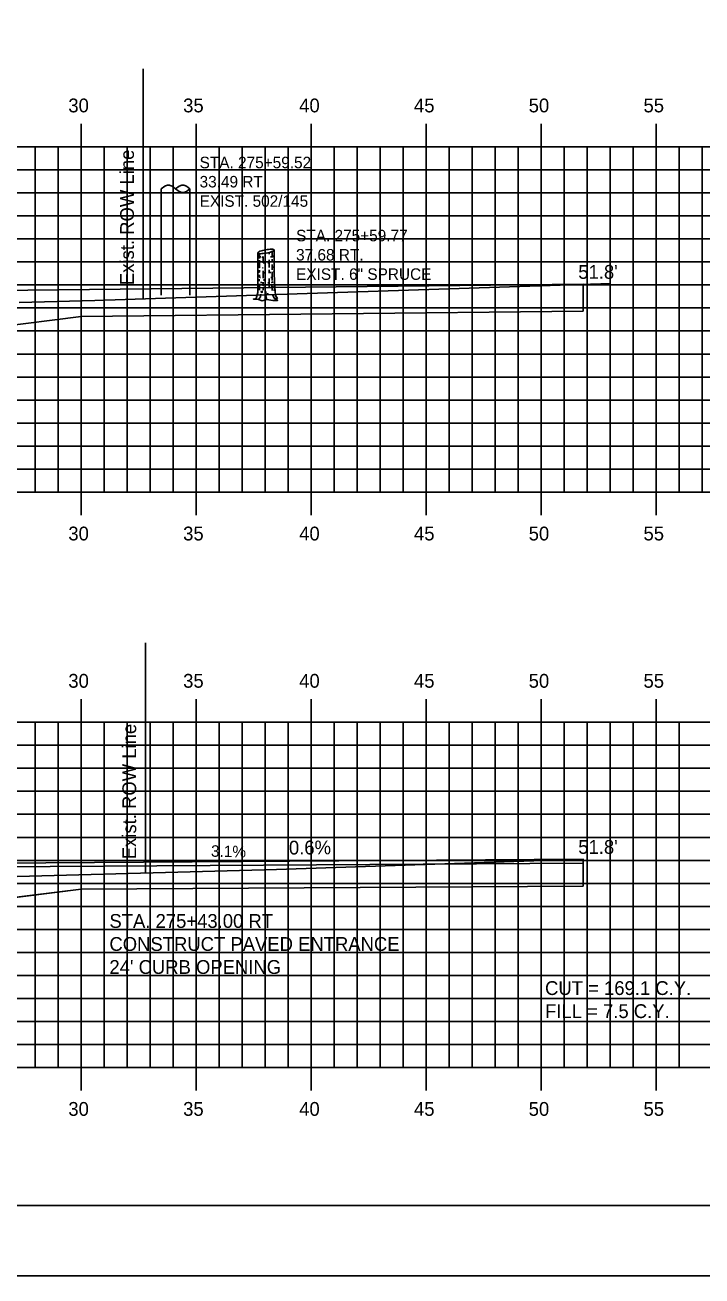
# Model space of a CAD drawing. Extents: x 853563 to 853733, y 366268 to 366378.
# Drawn here: x 853673.3 to 853702.8, y 366268.2 to 366322.5 of the extents above; entities that cross this region are included whole.
import ezdxf

# ---------------------------------------------------------------- set-up
doc = ezdxf.new("R2010")
doc.units = 0
for name, color, linetype in [('ANNOTATION', 7, 'Continuous'), ('BORDER', 7, 'Continuous'), ('D_Roadway_Drive_Gravel_RT', 7, 'Continuous'), ('D_Roadway_Drive_SubGrade', 7, 'Continuous'), ('D_Text_Monospaced', 7, 'Continuous'), ('D_Text_Standard', 7, 'Continuous'), ('E_ROW_Line', 7, 'Continuous'), ('H_V ANNOTATION', 7, 'Continuous'), ('JUNK COM EXC', 7, 'Continuous'), ('MAJOR', 7, 'Continuous'), ('MINOR', 7, 'Continuous'), ('PLOT BOUNDARY', 7, 'Continuous'), ('S_Roadway_Centerline', 7, 'Continuous'), ('S_Trees_Conifer_NonPay', 7, 'Continuous'), ('S_Utilities_Pole_Power', 7, 'Continuous')]:
    doc.layers.add(name, color=color, linetype=linetype)

msp = doc.modelspace()

# ---------------------------------------------------------------- linework, layer by layer
at = {"layer": 'BORDER'}
msp.add_line((853570.768, 366271.236), (853730.768, 366271.236), dxfattribs=at)
at = {"layer": 'D_Roadway_Drive_Gravel_RT'}
for p, q in [((853669.768, 366310.963), (853697.603, 366311.267)), ((853675.768, 366309.862), (853697.603, 366310.1)), ((853669.764, 366286.106), (853697.603, 366286.284)), ((853669.765, 366285.939), (853697.603, 366286.117)), ((853675.768, 366284.977), (853697.603, 366285.117))]:
    msp.add_line(p, q, dxfattribs=at)
at = {"layer": 'D_Roadway_Drive_SubGrade'}
for p, q in [((853697.603, 366311.267), (853697.603, 366310.1)), ((853665.758, 366308.61), (853675.768, 366309.862)), ((853697.603, 366286.284), (853697.603, 366285.117)), ((853665.774, 366283.753), (853675.768, 366284.977))]:
    msp.add_line(p, q, dxfattribs=at)
at = {"layer": 'E_ROW_Line'}
for p, q in [((853678.469, 366310.63), (853678.469, 366320.63)), ((853678.565, 366285.683), (853678.565, 366295.683))]:
    msp.add_line(p, q, dxfattribs=at)
at = {"layer": 'JUNK COM EXC'}
msp.add_lwpolyline([(853697.603, 366285.117), (853697.603, 366286.284), (853684.27, 366285.84), (853672.991, 366285.531), (853672.225, 366285.511), (853671.472, 366285.595), (853665.766, 366285.75), (853665.774, 366283.753), (853675.768, 366284.977), (853697.603, 366285.117)], dxfattribs=at)
at = {"layer": 'MAJOR'}
for p, q in [((853675.768, 366318.238), (853675.768, 366317.236)), ((853680.768, 366318.238), (853680.768, 366317.236)), ((853685.768, 366318.238), (853685.768, 366317.236)), ((853690.768, 366318.238), (853690.768, 366317.236)), ((853695.768, 366318.238), (853695.768, 366317.236)), ((853700.768, 366318.238), (853700.768, 366317.236)), ((853575.768, 366317.236), (853715.768, 366317.236)), ((853575.768, 366317.236), (853715.768, 366317.236)), ((853675.768, 366302.236), (853675.768, 366317.236)), ((853680.768, 366302.236), (853680.768, 366317.236)), ((853685.768, 366302.236), (853685.768, 366317.236)), ((853690.768, 366302.236), (853690.768, 366317.236)), ((853695.768, 366302.236), (853695.768, 366317.236)), ((853700.768, 366302.236), (853700.768, 366317.236)), ((853575.768, 366312.236), (853715.768, 366312.236)), ((853575.768, 366307.236), (853715.768, 366307.236)), ((853575.768, 366302.236), (853715.768, 366302.236)), ((853575.768, 366302.236), (853715.768, 366302.236)), ((853675.768, 366301.234), (853675.768, 366302.236)), ((853680.768, 366301.234), (853680.768, 366302.236)), ((853685.768, 366301.234), (853685.768, 366302.236)), ((853690.768, 366301.234), (853690.768, 366302.236)), ((853695.768, 366301.234), (853695.768, 366302.236)), ((853700.768, 366301.234), (853700.768, 366302.236)), ((853675.768, 366293.238), (853675.768, 366292.236)), ((853680.768, 366293.238), (853680.768, 366292.236)), ((853685.768, 366293.238), (853685.768, 366292.236)), ((853690.768, 366293.238), (853690.768, 366292.236)), ((853695.768, 366293.238), (853695.768, 366292.236)), ((853700.768, 366293.238), (853700.768, 366292.236)), ((853575.768, 366292.236), (853715.768, 366292.236)), ((853575.768, 366292.236), (853715.768, 366292.236)), ((853675.768, 366277.236), (853675.768, 366292.236)), ((853680.768, 366277.236), (853680.768, 366292.236)), ((853685.768, 366277.236), (853685.768, 366292.236)), ((853690.768, 366277.236), (853690.768, 366292.236)), ((853695.768, 366277.236), (853695.768, 366292.236)), ((853700.768, 366277.236), (853700.768, 366292.236)), ((853575.768, 366287.236), (853715.768, 366287.236)), ((853575.768, 366282.236), (853715.768, 366282.236)), ((853575.768, 366277.236), (853715.768, 366277.236)), ((853575.768, 366277.236), (853715.768, 366277.236)), ((853675.768, 366276.234), (853675.768, 366277.236)), ((853680.768, 366276.234), (853680.768, 366277.236)), ((853685.768, 366276.234), (853685.768, 366277.236)), ((853690.768, 366276.234), (853690.768, 366277.236)), ((853695.768, 366276.234), (853695.768, 366277.236)), ((853700.768, 366276.234), (853700.768, 366277.236))]:
    msp.add_line(p, q, dxfattribs=at)
at = {"layer": 'MINOR'}
for p, q in [((853673.768, 366302.236), (853673.768, 366317.236)), ((853674.768, 366302.236), (853674.768, 366317.236)), ((853676.768, 366302.236), (853676.768, 366317.236)), ((853677.768, 366302.236), (853677.768, 366317.236)), ((853678.768, 366302.236), (853678.768, 366317.236)), ((853679.768, 366302.236), (853679.768, 366317.236)), ((853681.768, 366302.236), (853681.768, 366317.236)), ((853682.768, 366302.236), (853682.768, 366317.236)), ((853683.768, 366302.236), (853683.768, 366317.236)), ((853684.768, 366302.236), (853684.768, 366317.236)), ((853686.768, 366302.236), (853686.768, 366317.236)), ((853687.768, 366302.236), (853687.768, 366317.236)), ((853688.768, 366302.236), (853688.768, 366317.236)), ((853689.768, 366302.236), (853689.768, 366317.236)), ((853691.768, 366302.236), (853691.768, 366317.236)), ((853692.768, 366302.236), (853692.768, 366317.236)), ((853693.768, 366302.236), (853693.768, 366317.236)), ((853694.768, 366302.236), (853694.768, 366317.236)), ((853696.768, 366302.236), (853696.768, 366317.236)), ((853697.768, 366302.236), (853697.768, 366317.236)), ((853698.768, 366302.236), (853698.768, 366317.236)), ((853699.768, 366302.236), (853699.768, 366317.236)), ((853701.768, 366302.236), (853701.768, 366317.236)), ((853702.768, 366302.236), (853702.768, 366317.236)), ((853575.768, 366316.236), (853715.768, 366316.236)), ((853575.768, 366315.236), (853715.768, 366315.236)), ((853575.768, 366314.236), (853715.768, 366314.236)), ((853575.768, 366313.236), (853715.768, 366313.236)), ((853575.768, 366311.236), (853715.768, 366311.236)), ((853575.768, 366310.236), (853715.768, 366310.236)), ((853575.768, 366309.236), (853715.768, 366309.236)), ((853575.768, 366308.236), (853715.768, 366308.236)), ((853575.768, 366306.236), (853715.768, 366306.236)), ((853575.768, 366305.236), (853715.768, 366305.236)), ((853575.768, 366304.236), (853715.768, 366304.236)), ((853575.768, 366303.236), (853715.768, 366303.236)), ((853673.768, 366277.236), (853673.768, 366292.236)), ((853674.768, 366277.236), (853674.768, 366292.236)), ((853676.768, 366277.236), (853676.768, 366292.236)), ((853677.768, 366277.236), (853677.768, 366292.236)), ((853678.768, 366277.236), (853678.768, 366292.236)), ((853679.768, 366277.236), (853679.768, 366292.236)), ((853681.768, 366277.236), (853681.768, 366292.236)), ((853682.768, 366277.236), (853682.768, 366292.236)), ((853683.768, 366277.236), (853683.768, 366292.236)), ((853684.768, 366277.236), (853684.768, 366292.236)), ((853686.768, 366277.236), (853686.768, 366292.236)), ((853687.768, 366277.236), (853687.768, 366292.236)), ((853688.768, 366277.236), (853688.768, 366292.236)), ((853689.768, 366277.236), (853689.768, 366292.236)), ((853691.768, 366277.236), (853691.768, 366292.236)), ((853692.768, 366277.236), (853692.768, 366292.236)), ((853693.768, 366277.236), (853693.768, 366292.236)), ((853694.768, 366277.236), (853694.768, 366292.236)), ((853696.768, 366277.236), (853696.768, 366292.236)), ((853697.768, 366277.236), (853697.768, 366292.236)), ((853698.768, 366277.236), (853698.768, 366292.236)), ((853699.768, 366277.236), (853699.768, 366292.236)), ((853701.768, 366277.236), (853701.768, 366292.236)), ((853575.768, 366291.236), (853715.768, 366291.236)), ((853575.768, 366290.236), (853715.768, 366290.236)), ((853575.768, 366289.236), (853715.768, 366289.236)), ((853575.768, 366288.236), (853715.768, 366288.236)), ((853575.768, 366286.236), (853715.768, 366286.236)), ((853575.768, 366285.236), (853715.768, 366285.236)), ((853575.768, 366284.236), (853715.768, 366284.236)), ((853575.768, 366283.236), (853715.768, 366283.236)), ((853575.768, 366281.236), (853715.768, 366281.236)), ((853575.768, 366280.236), (853715.768, 366280.236)), ((853575.768, 366279.236), (853715.768, 366279.236)), ((853575.768, 366278.236), (853715.768, 366278.236))]:
    msp.add_line(p, q, dxfattribs=at)
at = {"layer": 'PLOT BOUNDARY'}
msp.add_lwpolyline([(853562.674, 366268.177), (853732.674, 366268.177), (853732.674, 366378.177), (853562.674, 366378.177)], close=True, dxfattribs=at)
at = {"layer": 'S_Roadway_Centerline'}
for points in [[(853673.078, 366310.47), (853676.362, 366310.56), (853698.798, 366311.307)], [(853672.991, 366285.531), (853684.27, 366285.84), (853697.603, 366286.284)]]:
    msp.add_lwpolyline(points, dxfattribs=at)
at = {"layer": 'S_Trees_Conifer_NonPay'}
for p, q in [((853683.53, 366312.596), (853683.53, 366312.39)), ((853683.687, 366312.471), (853683.687, 366312.197)), ((853683.949, 366312.651), (853683.949, 366312.572)), ((853684.083, 366312.362), (853684.083, 366312.232)), ((853683.53, 366312.318), (853683.53, 366311.986)), ((853683.53, 366311.872), (853683.53, 366311.793)), ((853683.687, 366311.844), (853683.687, 366311.526)), ((853683.949, 366312.323), (853683.949, 366311.997)), ((853683.949, 366311.896), (853683.949, 366311.743)), ((853684.083, 366312.123), (853684.083, 366311.896)), ((853684.083, 366311.804), (853684.083, 366311.428)), ((853683.513, 366311.492), (853683.513, 366311.395)), ((853683.53, 366311.679), (853683.53, 366311.569)), ((853683.53, 366311.281), (853683.53, 366311.013)), ((853683.687, 366311.356), (853683.687, 366311.196)), ((853683.728, 366311.481), (853683.728, 366311.411)), ((853683.949, 366311.514), (853683.949, 366311.281)), ((853683.687, 366311.138), (853683.687, 366311.007)), ((853683.949, 366311.218), (853683.949, 366311.132)), ((853684.065, 366311.235), (853684.082, 366310.99)), ((853684.144, 366311.007), (853684.204, 366311.014))]:
    msp.add_line(p, q, dxfattribs=at)
for points in [[(853683.452, 366312.63), (853683.452, 366310.912), (853683.382, 366310.655), (853683.263, 366310.621), (853683.479, 366310.605), (853683.639, 366310.547), (853683.848, 366310.605), (853684.11, 366310.558), (853684.316, 366310.564), (853684.165, 366310.667), (853684.093, 366310.82)], [(853684.083, 366312.692), (853684.083, 366312.594), (853684.083, 366312.43)], [(853684.194, 366310.646), (853684.31, 366310.655), (853684.219, 366310.781), (853684.185, 366311.321), (853684.165, 366311.839), (853684.165, 366312.758)], [(853683.479, 366310.605), (853683.569, 366310.717), (853683.586, 366310.831)], [(853683.61, 366310.968), (853683.599, 366310.923), (853683.65, 366310.912), (853683.65, 366310.974)], [(853683.848, 366310.605), (853683.803, 366310.781), (853683.797, 366310.945)], [(853683.801, 366310.831), (853683.871, 366310.825), (853683.889, 366310.878)]]:
    msp.add_lwpolyline(points, dxfattribs=at)
for centre, radius, start, end in [((853683.466, 366312.63), 0.0141, 174.3267, 190.3798), ((853683.47, 366312.63), 0.0186, 160.3798, 174.3267), ((853683.466, 366312.63), 0.0141, 190.3798, 206.433), ((853683.466, 366312.514), 0.0143, 180, 196.0515), ((853683.477, 366312.627), 0.0263, 141.6195, 160.3798), ((853683.47, 366312.632), 0.0186, 206.433, 220.3798), ((853683.475, 366312.637), 0.0263, 220.3798, 239.1402), ((853683.514, 366312.598), 0.0729, 130.3798, 141.6195), ((853683.499, 366312.677), 0.0729, 239.1402, 250.3798), ((853683.625, 366312.467), 0.245, 108.3946, 130.3798), ((853683.557, 366312.839), 0.245, 250.3798, 272.3651), ((853683.594, 366312.703), 0.245, 254.8461, 261.8968), ((853684.124, 366310.967), 1.825, 100.3798, 108.3946), ((853683.809, 366314.21), 1.767, 261.8968, 262.605), ((853683.492, 366314.418), 1.825, 272.3651, 280.3798), ((853683.809, 366314.21), 1.767, 264.3267, 266.0499), ((853684.124, 366310.967), 1.825, 92.3651, 100.3798), ((853683.492, 366314.418), 1.825, 280.3798, 288.3946), ((853683.809, 366314.21), 1.767, 276.2449, 278.1032), ((853684.059, 366312.546), 0.245, 70.3798, 92.3651), ((853684.023, 366312.703), 0.245, 278.1032, 284.1859), ((853683.991, 366312.919), 0.245, 288.3946, 310.3798), ((853684.023, 366312.703), 0.245, 291.7653, 300), ((853684.117, 366312.708), 0.0729, 59.1402, 70.3798), ((853684.109, 366312.555), 0.0738, 300, 311.2506), ((853684.102, 366312.787), 0.0729, 310.3798, 321.6195), ((853684.141, 366312.748), 0.0263, 40.3798, 59.1402), ((853684.14, 366312.519), 0.0267, 311.2506, 330), ((853684.139, 366312.759), 0.0263, 321.6195, 340.3798), ((853684.147, 366312.753), 0.0186, 26.433, 40.3798), ((853684.151, 366312.755), 0.0141, 10.3798, 26.433), ((853684.146, 366312.515), 0.0189, 330, 343.9485), ((853684.151, 366312.755), 0.0141, 354.3267, 10.3798), ((853684.146, 366312.756), 0.0186, 340.3798, 354.3267), ((853683.466, 366312.048), 0.0143, 180, 196.0515), ((853683.467, 366311.837), 0.0143, 180, 196.0515), ((853683.471, 366312.049), 0.0189, 196.0515, 210), ((853683.471, 366311.838), 0.0189, 196.0515, 210), ((853683.478, 366312.053), 0.0267, 210, 228.7494), ((853683.478, 366311.842), 0.0267, 210, 228.7494), ((853683.509, 366312.089), 0.0738, 228.7494, 240), ((853683.509, 366311.877), 0.0738, 228.7494, 240), ((853683.594, 366312.237), 0.245, 240, 246.7914), ((853683.594, 366312.025), 0.245, 240, 254.9514), ((853683.596, 366312.45), 0.245, 244.3148, 257.5375), ((853683.594, 366312.237), 0.245, 254.8461, 257.5454), ((853683.809, 366313.744), 1.767, 265.2285, 266.1325), ((853683.81, 366313.958), 1.767, 265.8991, 267.5962), ((853683.81, 366313.958), 1.767, 272.7221, 274.4847), ((853684.023, 366312.237), 0.245, 284.1859, 300), ((853684.023, 366312.025), 0.245, 292.1924, 300), ((853684.109, 366312.089), 0.0738, 300, 311.2506), ((853684.109, 366311.877), 0.0738, 300, 311.2506), ((853684.14, 366312.053), 0.0267, 311.2506, 330), ((853684.14, 366311.842), 0.0267, 311.2506, 330), ((853684.141, 366312.267), 0.0267, 311.2506, 330), ((853684.146, 366312.049), 0.0189, 330, 343.9485), ((853684.147, 366311.838), 0.0189, 330, 343.9485), ((853684.148, 366312.263), 0.0189, 330, 343.9485), ((853683.466, 366311.4), 0.0143, 180, 196.0515), ((853683.593, 366311.806), 0.245, 254.9814, 261.8968), ((853683.808, 366313.313), 1.767, 261.8968, 262.45), ((853683.808, 366313.096), 1.767, 262.2622, 265.0496), ((853683.809, 366313.533), 1.767, 266.0429, 268.5525), ((853683.808, 366313.096), 1.767, 272.6293, 274.5612), ((853683.809, 366313.533), 1.767, 274.5361, 277.0026), ((853683.808, 366313.313), 1.767, 276.7966, 278.1032), ((853683.808, 366313.096), 1.767, 277.63, 278.1032), ((853684.023, 366311.806), 0.245, 278.1032, 284.3207), ((853684.023, 366311.589), 0.245, 278.1032, 294.6056), ((853683.465, 366311.195), 0.0143, 180, 196.0515), ((853683.47, 366311.196), 0.0189, 196.0515, 210), ((853683.476, 366311.2), 0.0267, 210, 228.7494), ((853683.507, 366311.235), 0.0738, 228.7494, 240), ((853683.593, 366311.383), 0.245, 240, 249.1675), ((853683.807, 366312.891), 1.767, 266.0862, 268.2187), ((853683.807, 366312.891), 1.767, 274.2776, 276.3006), ((853684.022, 366311.383), 0.245, 284.0684, 300), ((853684.108, 366311.235), 0.0738, 300, 302.05)]:
    msp.add_arc(centre, radius, start, end, dxfattribs=at)
at = {"layer": 'S_Utilities_Pole_Power'}
for p, q in [((853679.256, 366310.793), (853679.253, 366315.413)), ((853679.256, 366315.413), (853679.413, 366315.523)), ((853679.725, 366315.523), (853679.881, 366315.413)), ((853680.038, 366315.523), (853679.881, 366315.413)), ((853679.881, 366315.413), (853680.038, 366315.302)), ((853680.506, 366315.413), (853680.35, 366315.523)), ((853680.35, 366315.302), (853680.506, 366315.413)), ((853680.506, 366310.793), (853680.503, 366315.413))]:
    msp.add_line(p, q, dxfattribs=at)
for centre, start, end in [((853679.569, 366315.302), 90, 125.2644), ((853679.569, 366315.302), 54.7356, 90), ((853680.194, 366315.302), 90, 125.2644), ((853680.194, 366315.523), 234.7356, 270), ((853680.194, 366315.302), 54.7356, 90), ((853680.194, 366315.523), 270, 305.2644)]:
    msp.add_arc(centre, 0.271, start, end, dxfattribs=at)

# ---------------------------------------------------------------- texts
at = {"layer": 'ANNOTATION'}
msp.add_text('0.6%', height=0.6, rotation=0.3661, dxfattribs=at).set_placement((853684.809, 366286.488))
for s, p in [('STA. 275+43.00 RT', (853677.003, 366283.302)), ('CONSTRUCT PAVED ENTRANCE', (853677.003, 366282.302)), ("24' CURB OPENING", (853677.003, 366281.302)), ('CUT = 169.1 C.Y.', (853695.944, 366280.386)), ('FILL = 7.5 C.Y.', (853695.944, 366279.384))]:
    msp.add_text(s, height=0.6, dxfattribs=at).set_placement(p)
at = {"layer": 'D_Text_Monospaced'}
for s, height, p in [('STA. 275+59.52', 0.49998, (853680.923, 366316.307)), ('33.49 RT.', 0.5, (853680.923, 366315.473)), ('EXIST. 502/145', 0.49998, (853680.923, 366314.633)), ('STA. 275+59.77', 0.49998, (853685.118, 366313.132)), ('37.68 RT.', 0.5, (853685.118, 366312.298)), ('EXIST. 6" SPRUCE', 0.49998, (853685.118, 366311.458))]:
    msp.add_text(s, height=height, dxfattribs=at).set_placement(p)
msp.add_text('3.1%', height=0.5, rotation=358.8098, dxfattribs=at).set_placement((853681.414, 366286.394))
at = {"layer": 'D_Text_Standard'}
for p in [(853697.388, 366311.503), (853697.388, 366286.519)]:
    msp.add_text("51.8'", height=0.6, dxfattribs=at).set_placement(p)
at = {"layer": 'E_ROW_Line'}
for p in [(853678.069, 366311.23), (853678.165, 366286.283)]:
    msp.add_text('Exist. ROW Line', height=0.6, rotation=90, dxfattribs=at).set_placement(p)
at = {"layer": 'H_V ANNOTATION'}
for s, p in [('30', (853675.216, 366318.736)), ('35', (853680.208, 366318.736)), ('40', (853685.254, 366318.736)), ('45', (853690.246, 366318.736)), ('50', (853695.232, 366318.736)), ('55', (853700.224, 366318.736)), ('30', (853675.216, 366300.136)), ('35', (853680.208, 366300.136)), ('40', (853685.254, 366300.136)), ('45', (853690.246, 366300.136)), ('50', (853695.232, 366300.136)), ('55', (853700.224, 366300.136)), ('30', (853675.216, 366293.736)), ('35', (853680.208, 366293.736)), ('40', (853685.254, 366293.736)), ('45', (853690.246, 366293.736)), ('50', (853695.232, 366293.736)), ('55', (853700.224, 366293.736)), ('30', (853675.216, 366275.136)), ('35', (853680.208, 366275.136)), ('40', (853685.254, 366275.136)), ('45', (853690.246, 366275.136)), ('50', (853695.232, 366275.136)), ('55', (853700.224, 366275.136))]:
    msp.add_text(s, height=0.6, dxfattribs=at).set_placement(p)

doc.saveas('drawing.dxf')
